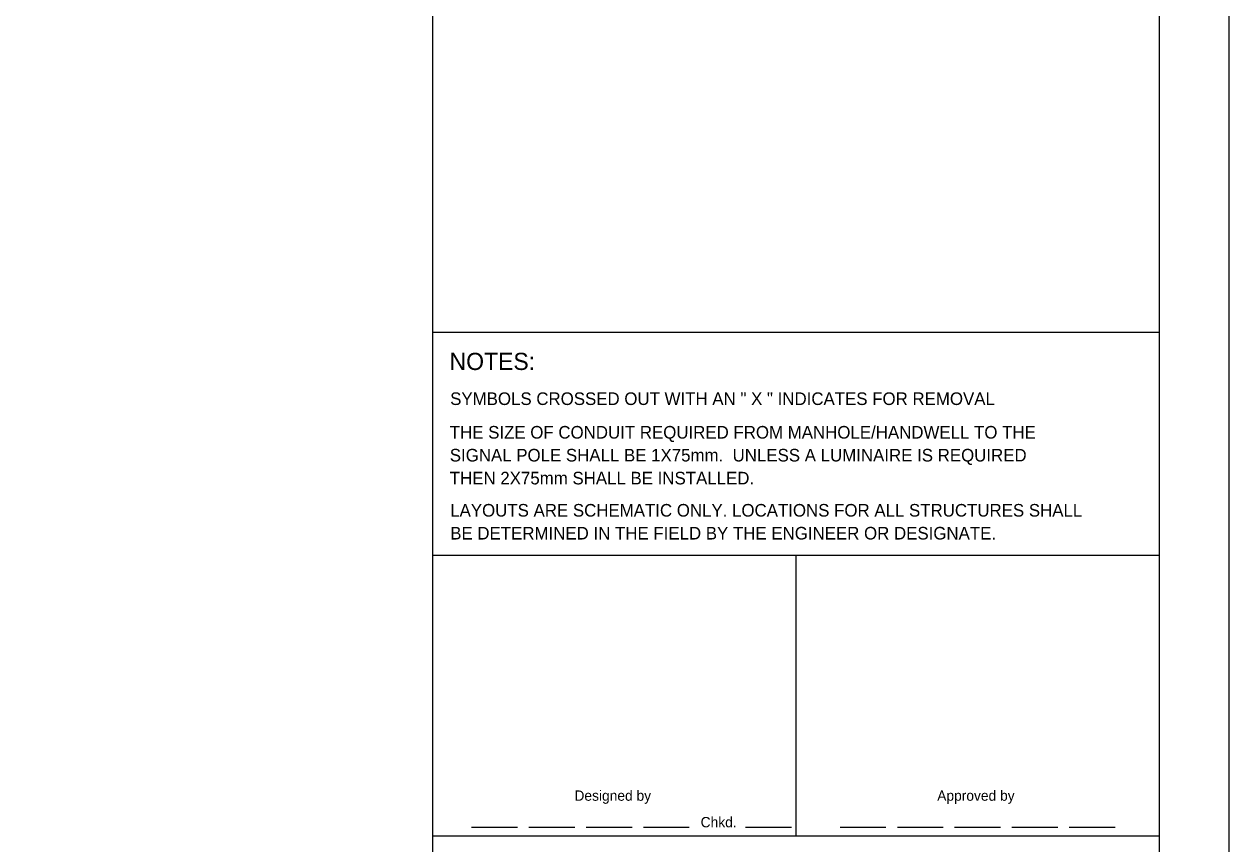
# Model space of a CAD drawing. Extents: x 612883 to 613093, y 4825734 to 4825879.
# Drawn here: x 613040.6 to 613093.1, y 4825770.5 to 4825806.3 of the extents above; entities that cross this region are included whole.
import ezdxf

# ---------------------------------------------------------------- set-up
doc = ezdxf.new("R2010")
doc.units = 0
for name, color, linetype in [('G-ANNO-LEGN', 7, 'Continuous'), ('G-ANNO-STMP', 7, 'Continuous'), ('G-TTLB-OTLN', 7, 'Continuous'), ('G-TTLB-OTLN-PB', 7, 'Continuous')]:
    doc.layers.add(name, color=color, linetype=linetype)

msp = doc.modelspace()

# ---------------------------------------------------------------- linework, layer by layer
at = {"layer": 'G-ANNO-STMP'}
for p, q in [((613060.093, 4825771.219), (613062.093, 4825771.219)), ((613062.593, 4825771.219), (613064.593, 4825771.219)), ((613065.093, 4825771.219), (613067.093, 4825771.219)), ((613067.593, 4825771.219), (613069.593, 4825771.219)), ((613072.047, 4825771.219), (613074.047, 4825771.219)), ((613076.175, 4825771.219), (613078.175, 4825771.219)), ((613078.675, 4825771.219), (613080.675, 4825771.218)), ((613081.175, 4825771.218), (613083.175, 4825771.218)), ((613083.675, 4825771.218), (613085.675, 4825771.218)), ((613086.175, 4825771.218), (613088.175, 4825771.218))]:
    msp.add_line(p, q, dxfattribs=at)
at = {"layer": 'G-TTLB-OTLN'}
for p, q in [((613058.399, 4825734.927), (613058.399, 4825869.211)), ((613058.399, 4825792.826), (613090.1, 4825792.826)), ((613090.1, 4825783.084), (613058.399, 4825783.084)), ((613074.25, 4825783.084), (613074.25, 4825770.827)), ((613090.1, 4825770.827), (613058.399, 4825770.827))]:
    msp.add_line(p, q, dxfattribs=at)
msp.add_lwpolyline([(612893.053, 4825869.211), (613090.1, 4825869.211), (613090.1, 4825734.927), (612893.053, 4825734.927)], close=True, dxfattribs=at)
at = {"layer": 'G-TTLB-OTLN-PB'}
msp.add_lwpolyline([(612882.799, 4825870.511), (613093.146, 4825870.511), (613093.146, 4825733.627), (612882.799, 4825733.627)], close=True, dxfattribs=at)

# ---------------------------------------------------------------- texts
at = {"layer": 'G-ANNO-LEGN'}
for s, height, p in [('NOTES:', 0.75, (613059.13, 4825791.173)), ('SYMBOLS CROSSED OUT WITH AN " X " INDICATES FOR REMOVAL', 0.55, (613059.156, 4825789.645)), ('THE SIZE OF CONDUIT REQUIRED FROM MANHOLE/HANDWELL TO THE', 0.55, (613059.139, 4825788.18)), ('SIGNAL POLE SHALL BE 1X75mm.  UNLESS A LUMINAIRE IS REQUIRED ', 0.55, (613059.139, 4825787.18)), ('THEN 2X75mm SHALL BE INSTALLED.', 0.55, (613059.139, 4825786.18)), ('LAYOUTS ARE SCHEMATIC ONLY. LOCATIONS FOR ALL STRUCTURES SHALL', 0.55, (613059.158, 4825784.776)), ('BE DETERMINED IN THE FIELD BY THE ENGINEER OR DESIGNATE.', 0.55, (613059.158, 4825783.776))]:
    msp.add_text(s, height=height, rotation=359.9998, dxfattribs=at).set_placement(p)
at = {"layer": 'G-ANNO-STMP'}
for s, p in [('Designed by', (613064.58, 4825772.376)), ('Approved by', (613080.414, 4825772.376)), ('Chkd.', (613070.089, 4825771.218))]:
    msp.add_text(s, height=0.45, dxfattribs=at).set_placement(p)

doc.saveas('drawing.dxf')
